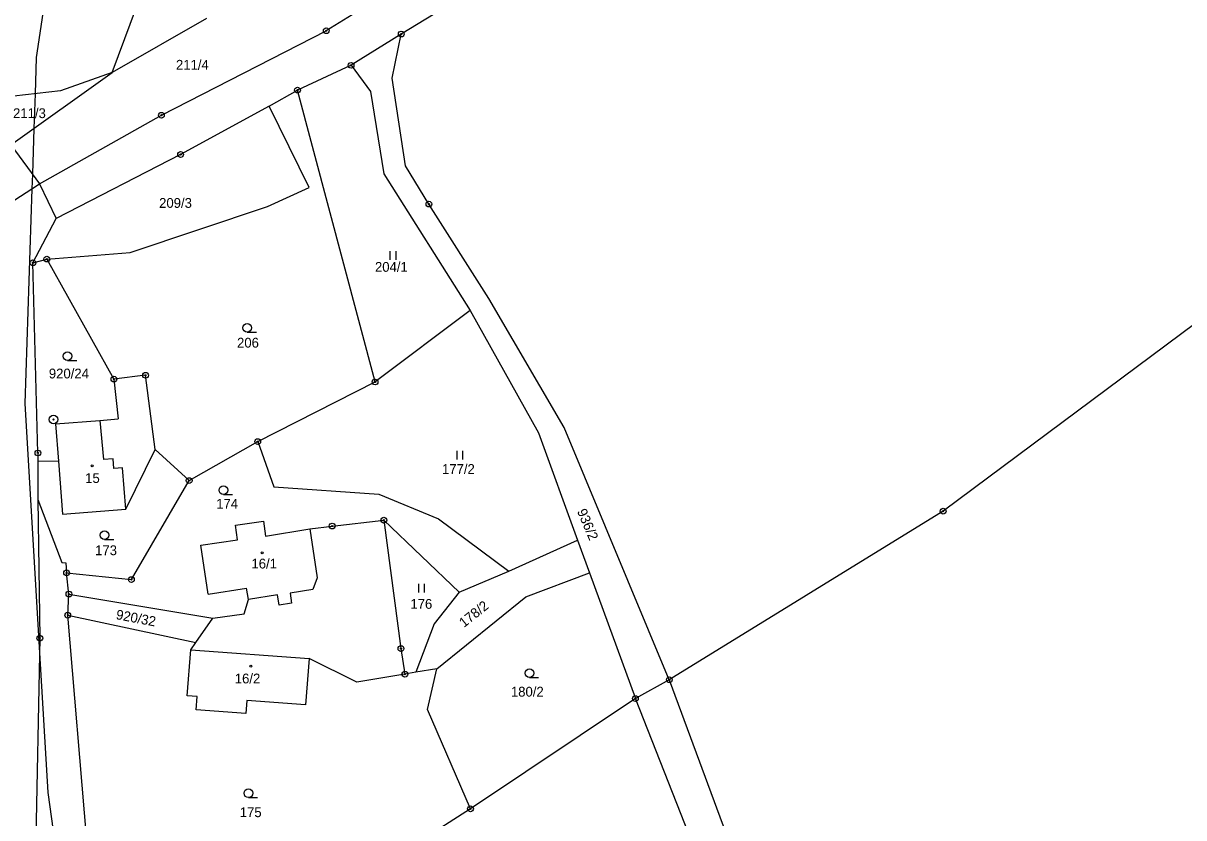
# Model space of a CAD drawing. Extents: x -547623 to -538651, y -1096714 to -1086522.
# Drawn here: x -544649.8 to -544448.5, y -1092940.9 to -1092803 of the extents above; entities that cross this region are included whole.
import ezdxf

# ---------------------------------------------------------------- set-up
doc = ezdxf.new("R2010")
doc.units = 0
for name, color, linetype in [('Vrstva 1', 7, 'Continuous'), ('Vrstva 25', 7, 'Continuous'), ('Vrstva 33', 7, 'Continuous'), ('Vrstva 52', 7, 'Continuous'), ('Vrstva 83', 7, 'Continuous'), ('Vrstva 86', 7, 'Continuous'), ('Vrstva 90', 7, 'Continuous'), ('Vrstva 92', 7, 'Continuous')]:
    doc.layers.add(name, color=color, linetype=linetype)

msp = doc.modelspace()

# ---------------------------------------------------------------- linework, layer by layer
at = {"layer": 'Vrstva 1'}
for points in [[(-544634.33, -1092811.6), (-544624.81, -1092785.88)], [(-544571.41, -1092797.07), (-544584.22, -1092804.91)], [(-544592.73, -1092801.58), (-544597.22, -1092804.34)], [(-544618.01, -1092802.22), (-544634.33, -1092811.6)], [(-544625.8, -1092819), (-544597.22, -1092804.34)], [(-544584.22, -1092804.91), (-544592.92, -1092810.34)], [(-544585.81, -1092812.59), (-544584.22, -1092804.91)], [(-544651.93, -1092824.15), (-544634.33, -1092811.6)], [(-544634.33, -1092811.6), (-544643.3, -1092814.74)], [(-544592.92, -1092810.34), (-544602.2, -1092814.63)], [(-544592.92, -1092810.34), (-544589.55, -1092814.9)], [(-544583.46, -1092827.77), (-544585.81, -1092812.59)], [(-544643.3, -1092814.74), (-544653.44, -1092815.93)], [(-544607.09, -1092817.45), (-544602.2, -1092814.63)], [(-544588.76, -1092865.29), (-544602.2, -1092814.63)], [(-544589.55, -1092814.9), (-544587.25, -1092829.16)], [(-544607.09, -1092817.45), (-544622.47, -1092825.82)], [(-544600.16, -1092831.56), (-544607.09, -1092817.45)], [(-544646.94, -1092830.9), (-544625.8, -1092819)], [(-544651.93, -1092824.15), (-544646.94, -1092830.9)], [(-544622.47, -1092825.82), (-544644.04, -1092836.9)], [(-544579.41, -1092834.42), (-544583.46, -1092827.77)], [(-544587.25, -1092829.16), (-544572.25, -1092852.86)], [(-544652.53, -1092834.53), (-544646.94, -1092830.9)], [(-544646.94, -1092830.9), (-544644.04, -1092836.9)], [(-544607.39, -1092834.82), (-544600.16, -1092831.56)], [(-544631.23, -1092842.8), (-544607.39, -1092834.82)], [(-544569.02, -1092850.8), (-544579.41, -1092834.42)], [(-544648.08, -1092844.6), (-544644.04, -1092836.9)], [(-544645.67, -1092843.96), (-544631.23, -1092842.8)], [(-544648.08, -1092844.6), (-544645.67, -1092843.96)], [(-544647.22, -1092877.61), (-544648.08, -1092844.6)], [(-544645.67, -1092843.96), (-544634.04, -1092864.79)], [(-544433.5, -1092845.43), (-544490.25, -1092887.71)], [(-544555.94, -1092873.21), (-544569.02, -1092850.8)], [(-544572.25, -1092852.86), (-544588.76, -1092865.29)], [(-544572.25, -1092852.86), (-544560.39, -1092874.12)], [(-544628.55, -1092864.13), (-544634.04, -1092864.79)], [(-544634.04, -1092864.79), (-544633.29, -1092871.71)], [(-544626.91, -1092877.01), (-544628.55, -1092864.13)], [(-544609.1, -1092875.63), (-544588.76, -1092865.29)], [(-544644.16, -1092872.55), (-544636.48, -1092871.96)], [(-544636.48, -1092871.96), (-544633.29, -1092871.71)], [(-544644.16, -1092872.55), (-544643.66, -1092879.03)], [(-544560.39, -1092874.12), (-544553.66, -1092892.72)], [(-544537.73, -1092916.96), (-544555.94, -1092873.21)], [(-544620.99, -1092882.4), (-544609.1, -1092875.63)], [(-544609.1, -1092875.63), (-544606.33, -1092883.51)], [(-544647.22, -1092877.61), (-544647.22, -1092879.11)], [(-544631.99, -1092887.36), (-544626.91, -1092877.01)], [(-544626.91, -1092877.01), (-544620.99, -1092882.4)], [(-544643.66, -1092879.03), (-544647.22, -1092879.11)], [(-544647.22, -1092879.11), (-544647.22, -1092885.66)], [(-544643.66, -1092879.03), (-544642.96, -1092888.2)], [(-544631, -1092899.57), (-544620.99, -1092882.4)], [(-544606.33, -1092883.51), (-544588.13, -1092884.73)], [(-544647.22, -1092885.66), (-544646.88, -1092909.74)], [(-544647.22, -1092885.66), (-544643.08, -1092896.62)], [(-544588.13, -1092884.73), (-544577.77, -1092889.05)], [(-544642.96, -1092888.2), (-544631.99, -1092887.36)], [(-544490.25, -1092887.71), (-544537.73, -1092916.96)], [(-544612.96, -1092890.13), (-544608.11, -1092889.45)], [(-544612.6, -1092892.7), (-544612.96, -1092890.13)], [(-544608.11, -1092889.45), (-544607.75, -1092892.03)], [(-544596.19, -1092890.28), (-544587.24, -1092889.26)], [(-544587.24, -1092889.26), (-544584.26, -1092911.55)], [(-544587.24, -1092889.26), (-544574.19, -1092901.77)], [(-544577.77, -1092889.05), (-544565.54, -1092898.11)], [(-544607.75, -1092892.03), (-544600.06, -1092890.76)], [(-544600.06, -1092890.76), (-544596.19, -1092890.28)], [(-544618.99, -1092893.61), (-544612.6, -1092892.7)], [(-544617.71, -1092902.11), (-544618.99, -1092893.61)], [(-544565.54, -1092898.11), (-544553.66, -1092892.72)], [(-544553.66, -1092892.72), (-544551.58, -1092898.39)], [(-544643.08, -1092896.62), (-544642.37, -1092896.67)], [(-544642.37, -1092896.67), (-544642.25, -1092898.41)], [(-544574.19, -1092901.77), (-544565.54, -1092898.11)], [(-544641.84, -1092902.08), (-544642.25, -1092898.41)], [(-544642.25, -1092898.41), (-544631, -1092899.57)], [(-544562.59, -1092902.56), (-544551.58, -1092898.39)], [(-544551.58, -1092898.39), (-544543.61, -1092920.23)], [(-544642.04, -1092905.75), (-544641.84, -1092902.08)], [(-544641.84, -1092902.08), (-544616.89, -1092906.28)], [(-544617.71, -1092902.11), (-544611.02, -1092901.04)], [(-544610.71, -1092903.01), (-544611.02, -1092901.04)], [(-544574.19, -1092901.77), (-544578.5, -1092907.24)], [(-544611.43, -1092905.53), (-544610.71, -1092903.01)], [(-544578.04, -1092915.06), (-544562.59, -1092902.56)], [(-544642.04, -1092905.75), (-544619.84, -1092910.49)], [(-544638.75, -1092944.86), (-544642.04, -1092905.75)], [(-544619.84, -1092910.49), (-544616.89, -1092906.28)], [(-544616.89, -1092906.28), (-544611.43, -1092905.53)], [(-544578.5, -1092907.24), (-544581.68, -1092915.64)], [(-544646.88, -1092909.74), (-544647.66, -1092947.21)], [(-544621.32, -1092919.76), (-544620.72, -1092911.74)], [(-544620.72, -1092911.74), (-544619.84, -1092910.49)], [(-544620.72, -1092911.74), (-544600.2, -1092913.28)], [(-544584.26, -1092911.55), (-544583.58, -1092915.98)], [(-544600.2, -1092913.28), (-544600.8, -1092921.3)], [(-544591.93, -1092917.37), (-544600.2, -1092913.28)], [(-544583.58, -1092915.98), (-544591.93, -1092917.37)], [(-544581.68, -1092915.64), (-544583.58, -1092915.98)], [(-544578.04, -1092915.06), (-544581.68, -1092915.64)], [(-544579.67, -1092922.12), (-544578.04, -1092915.06)], [(-544537.73, -1092916.96), (-544543.61, -1092920.23)], [(-544537.73, -1092916.96), (-544525.83, -1092949.2)], [(-544619.63, -1092919.89), (-544621.32, -1092919.76)], [(-544619.8, -1092922.17), (-544619.63, -1092919.89)], [(-544543.61, -1092920.23), (-544572.21, -1092939.36)], [(-544530.01, -1092954.76), (-544543.61, -1092920.23)], [(-544611.18, -1092922.82), (-544619.8, -1092922.17)], [(-544611.01, -1092920.53), (-544611.18, -1092922.82)], [(-544600.8, -1092921.3), (-544611.01, -1092920.53)], [(-544572.21, -1092939.36), (-544579.67, -1092922.12)], [(-544572.21, -1092939.36), (-544581.05, -1092945.02)]]:
    msp.add_lwpolyline(points, dxfattribs=at)
at = {"layer": 'Vrstva 25'}
for p, q in [((-544586.12, -1092844.11), (-544586.12, -1092842.61)), ((-544585.12, -1092844.11), (-544585.12, -1092842.61)), ((-544610.92, -1092856.64), (-544609.32, -1092856.64)), ((-544642.09, -1092861.54), (-544640.49, -1092861.54)), ((-544574.53, -1092878.76), (-544574.53, -1092877.26)), ((-544573.53, -1092878.76), (-544573.53, -1092877.26)), ((-544615.06, -1092884.82), (-544613.46, -1092884.82)), ((-544635.68, -1092892.62), (-544634.08, -1092892.62)), ((-544581.18, -1092901.83), (-544581.18, -1092900.33)), ((-544580.18, -1092901.83), (-544580.18, -1092900.33)), ((-544561.99, -1092916.56), (-544560.39, -1092916.56)), ((-544610.72, -1092937.41), (-544609.12, -1092937.41))]:
    msp.add_line(p, q, dxfattribs=at)
for centre, radius in [((-544610.92, -1092855.89), 0.75), ((-544642.09, -1092860.79), 0.75), ((-544637.81, -1092879.82), 0.175), ((-544615.06, -1092884.07), 0.75), ((-544635.68, -1092891.87), 0.75), ((-544608.32, -1092894.95), 0.175), ((-544610.31, -1092914.61), 0.175), ((-544561.99, -1092915.81), 0.75), ((-544610.72, -1092936.66), 0.75)]:
    msp.add_circle(centre, radius, dxfattribs=at)
at = {"layer": 'Vrstva 33'}
for points in [[(-544636.48, -1092871.96), (-544635.86, -1092878.73)], [(-544634.17, -1092878.6), (-544635.86, -1092878.73)], [(-544634.04, -1092880.3), (-544634.17, -1092878.6)], [(-544632.54, -1092880.18), (-544634.04, -1092880.3)], [(-544631.99, -1092887.36), (-544632.54, -1092880.18)], [(-544600.06, -1092890.76), (-544598.79, -1092899.26)], [(-544598.79, -1092899.26), (-544599.54, -1092901.3)], [(-544605.67, -1092902.24), (-544610.71, -1092903.01)], [(-544605.4, -1092904.02), (-544605.67, -1092902.24)], [(-544599.54, -1092901.3), (-544603.5, -1092901.91)], [(-544603.5, -1092901.91), (-544603.23, -1092903.69)], [(-544603.23, -1092903.69), (-544605.4, -1092904.02)]]:
    msp.add_lwpolyline(points, dxfattribs=at)
at = {"layer": 'Vrstva 52'}
msp.add_lwpolyline([(-544631.32, -1092700.49), (-544634.45, -1092721.44), (-544636.85, -1092737.58), (-544637.11, -1092739.28), (-544638.75, -1092750.31), (-544647.5, -1092809), (-544647.71, -1092815.26), (-544647.91, -1092821.28), (-544648.17, -1092829.23), (-544648.26, -1092831.76), (-544649.5, -1092869), (-544646.93, -1092912.31), (-544645.5, -1092936.5), (-544640.3, -1092973.97)], dxfattribs=at)
at = {"layer": 'Vrstva 83'}
for centre, radius in [((-544597.22, -1092804.34), 0.5), ((-544597.22, -1092804.34), 0.1), ((-544584.22, -1092804.91), 0.5), ((-544584.22, -1092804.91), 0.1), ((-544592.92, -1092810.34), 0.5), ((-544592.92, -1092810.34), 0.1), ((-544602.2, -1092814.63), 0.5), ((-544602.2, -1092814.63), 0.1), ((-544625.8, -1092819), 0.5), ((-544625.8, -1092819), 0.1), ((-544622.47, -1092825.82), 0.5), ((-544622.47, -1092825.82), 0.1), ((-544579.41, -1092834.42), 0.5), ((-544579.41, -1092834.42), 0.1), ((-544645.67, -1092843.96), 0.5), ((-544645.67, -1092843.96), 0.1), ((-544648.08, -1092844.6), 0.5), ((-544648.08, -1092844.6), 0.1), ((-544628.55, -1092864.13), 0.5), ((-544628.55, -1092864.13), 0.1), ((-544634.04, -1092864.79), 0.5), ((-544634.04, -1092864.79), 0.1), ((-544588.76, -1092865.29), 0.5), ((-544588.76, -1092865.29), 0.1), ((-544644.52, -1092871.79), 0.75), ((-544644.52, -1092871.79), 0.1), ((-544609.1, -1092875.63), 0.5), ((-544609.1, -1092875.63), 0.1), ((-544647.22, -1092877.61), 0.5), ((-544647.22, -1092877.61), 0.1), ((-544620.99, -1092882.4), 0.5), ((-544620.99, -1092882.4), 0.1), ((-544490.25, -1092887.71), 0.5), ((-544490.25, -1092887.71), 0.1), ((-544596.19, -1092890.28), 0.5), ((-544596.19, -1092890.28), 0.1), ((-544587.24, -1092889.26), 0.5), ((-544587.24, -1092889.26), 0.1), ((-544642.25, -1092898.41), 0.5), ((-544642.25, -1092898.41), 0.1), ((-544631, -1092899.57), 0.5), ((-544631, -1092899.57), 0.1), ((-544641.84, -1092902.08), 0.5), ((-544641.84, -1092902.08), 0.1), ((-544642.04, -1092905.75), 0.5), ((-544642.04, -1092905.75), 0.1), ((-544646.88, -1092909.74), 0.5), ((-544646.88, -1092909.74), 0.1), ((-544584.26, -1092911.55), 0.5), ((-544584.26, -1092911.55), 0.1), ((-544583.58, -1092915.98), 0.5), ((-544583.58, -1092915.98), 0.1), ((-544537.73, -1092916.96), 0.5), ((-544537.73, -1092916.96), 0.1), ((-544543.61, -1092920.23), 0.5), ((-544543.61, -1092920.23), 0.1), ((-544572.21, -1092939.36), 0.5), ((-544572.21, -1092939.36), 0.1)]:
    msp.add_circle(centre, radius, dxfattribs=at)
at = {"layer": 'Vrstva 90'}
for points in [[(-544644.16, -1092872.55), (-544636.48, -1092871.96)], [(-544636.48, -1092871.96), (-544635.86, -1092878.73)], [(-544644.16, -1092872.55), (-544643.66, -1092879.03)], [(-544643.66, -1092879.03), (-544642.96, -1092888.2)], [(-544634.17, -1092878.6), (-544635.86, -1092878.73)], [(-544634.04, -1092880.3), (-544634.17, -1092878.6)], [(-544632.54, -1092880.18), (-544634.04, -1092880.3)], [(-544631.99, -1092887.36), (-544632.54, -1092880.18)], [(-544642.96, -1092888.2), (-544631.99, -1092887.36)], [(-544612.96, -1092890.13), (-544608.11, -1092889.45)], [(-544612.6, -1092892.7), (-544612.96, -1092890.13)], [(-544608.11, -1092889.45), (-544607.75, -1092892.03)], [(-544607.75, -1092892.03), (-544600.06, -1092890.76)], [(-544600.06, -1092890.76), (-544598.79, -1092899.26)], [(-544618.99, -1092893.61), (-544612.6, -1092892.7)], [(-544617.71, -1092902.11), (-544618.99, -1092893.61)], [(-544598.79, -1092899.26), (-544599.54, -1092901.3)], [(-544617.71, -1092902.11), (-544611.02, -1092901.04)], [(-544610.71, -1092903.01), (-544611.02, -1092901.04)], [(-544605.67, -1092902.24), (-544610.71, -1092903.01)], [(-544605.4, -1092904.02), (-544605.67, -1092902.24)], [(-544599.54, -1092901.3), (-544603.5, -1092901.91)], [(-544603.5, -1092901.91), (-544603.23, -1092903.69)], [(-544603.23, -1092903.69), (-544605.4, -1092904.02)], [(-544621.32, -1092919.76), (-544620.72, -1092911.74)], [(-544620.72, -1092911.74), (-544600.2, -1092913.28)], [(-544600.2, -1092913.28), (-544600.8, -1092921.3)], [(-544619.63, -1092919.89), (-544621.32, -1092919.76)], [(-544619.8, -1092922.17), (-544619.63, -1092919.89)], [(-544611.18, -1092922.82), (-544619.8, -1092922.17)], [(-544611.01, -1092920.53), (-544611.18, -1092922.82)], [(-544600.8, -1092921.3), (-544611.01, -1092920.53)]]:
    msp.add_lwpolyline(points, dxfattribs=at)

# ---------------------------------------------------------------- texts
at = {"layer": 'Vrstva 86'}
for s, p in [('211/4', (-544623.28, -1092811.1)), ('211/3', (-544651.53, -1092819.5)), ('209/3', (-544626.2, -1092835.07)), ('204/1', (-544588.77, -1092846.17)), ('206', (-544612.69, -1092859.32)), ('920/24', (-544645.32, -1092864.67)), ('177/2', (-544577.15, -1092881.24)), ('174', (-544616.3, -1092887.27)), ('173', (-544637.3, -1092895.34)), ('176', (-544582.63, -1092904.65)), ('180/2', (-544565.2, -1092919.88)), ('175', (-544612.22, -1092940.8))]:
    msp.add_text(s, height=1.7, dxfattribs=at).set_placement(p)
for s, rotation, p in [('936/2', 292.9828, (-544553.77, -1092887.71)), ('178/2', 38.63, (-544573.34, -1092907.98)), ('920/32', 349.275, (-544633.78, -1092906.42))]:
    msp.add_text(s, height=1.7, rotation=rotation, dxfattribs=at).set_placement(p)
at = {"layer": 'Vrstva 92'}
for s, p in [('15', (-544639.02, -1092882.81)), ('16/1', (-544610.19, -1092897.65)), ('16/2', (-544613.08, -1092917.59))]:
    msp.add_text(s, height=1.7, dxfattribs=at).set_placement(p)

doc.saveas('drawing.dxf')
